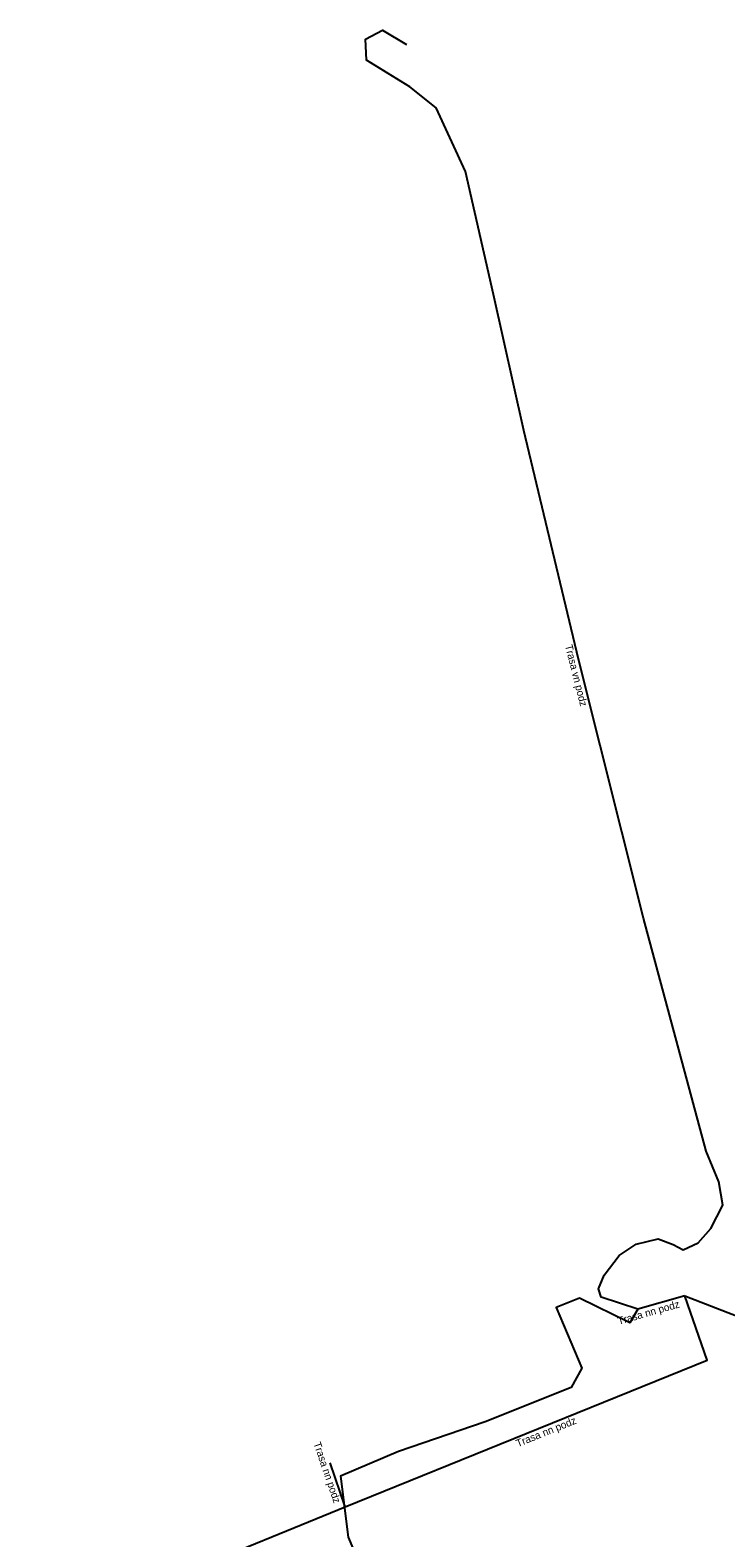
# Model space of a CAD drawing. Extents: x -710551 to -710032, y -1024932 to -1024617.
# Drawn here: x -710329 to -710282.5, y -1024738.3 to -1024637.4 of the extents above; entities that cross this region are included whole.
import ezdxf

# ---------------------------------------------------------------- set-up
doc = ezdxf.new("R2010")
doc.units = 0
for name, color, linetype in [('Popiskový text - Ostatní atributy Trasy', 7, 'Continuous'), ('Spojnice NN', 7, 'Continuous'), ('Spojnice VN', 7, 'Continuous')]:
    doc.layers.add(name, color=color, linetype=linetype)

msp = doc.modelspace()

# ---------------------------------------------------------------- linework, layer by layer
at = {"layer": 'Spojnice NN'}
for points in [[(-710285.2, -1024722.13), (-710281.63, -1024723.5), (-710269.43, -1024718.57)], [(-710307.9, -1024736.24), (-710283.7, -1024726.43), (-710285.2, -1024722.13)], [(-710285.2, -1024722.13), (-710288.33, -1024723.03)], [(-710307.9, -1024736.24), (-710308.9, -1024733.3)], [(-710328.96, -1024744.99), (-710318.79, -1024740.71), (-710307.9, -1024736.24)]]:
    msp.add_lwpolyline(points, dxfattribs=at)
at = {"layer": 'Spojnice VN'}
for points in [[(-710288.33, -1024723.03), (-710290.78, -1024722.22), (-710290.97, -1024721.65), (-710290.59, -1024720.74), (-710289.59, -1024719.44), (-710288.45, -1024718.66), (-710286.97, -1024718.31), (-710285.97, -1024718.7), (-710285.31, -1024719.05), (-710284.3, -1024718.59), (-710283.45, -1024717.62), (-710282.66, -1024716.06), (-710282.92, -1024714.5), (-710283.78, -1024712.45), (-710287.97, -1024696.85), (-710292.31, -1024679.53), (-710295.97, -1024664.23), (-710297.99, -1024655.13), (-710299.85, -1024646.91), (-710301.83, -1024642.64), (-710303.59, -1024641.24), (-710306.47, -1024639.45), (-710306.55, -1024638.05), (-710305.41, -1024637.44), (-710303.8, -1024638.41)], [(-710288.33, -1024723.03), (-710288.87, -1024723.94), (-710292.24, -1024722.29), (-710293.8, -1024722.91), (-710292.09, -1024726.96), (-710292.8, -1024728.27), (-710298.54, -1024730.56), (-710304.34, -1024732.55), (-710308.21, -1024734.19), (-710307.7, -1024738.27), (-710303.4, -1024748.42)]]:
    msp.add_lwpolyline(points, dxfattribs=at)

# ---------------------------------------------------------------- texts
at = {"layer": 'Popiskový text - Ostatní atributy Trasy'}
for s, rotation, p in [('Trasa vn podz', 284.0736, (-710293.21, -1024678.62)), ('Trasa nn podz', 15.9563, (-710289.61, -1024724.07)), ('Trasa nn podz', 22.0663, (-710296.36, -1024732.26)), ('Trasa nn podz', 288.785, (-710310.03, -1024732))]:
    msp.add_text(s, height=0.5, rotation=rotation, dxfattribs=at).set_placement(p)

doc.saveas('drawing.dxf')
